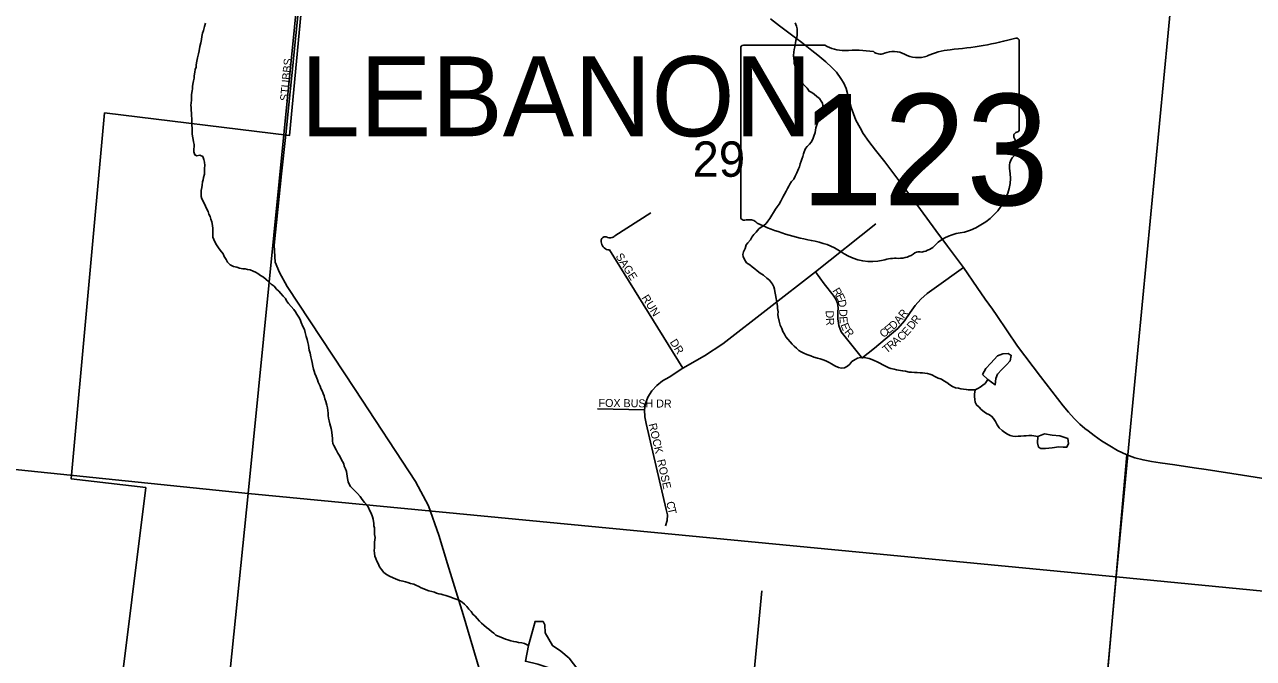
# Model space of a CAD drawing. Extents: x 1310247 to 1664935, y 284496 to 704931.
# Drawn here: x 1490025 to 1497704, y 520097 to 524060 of the extents above; entities that cross this region are included whole.
import ezdxf

# ---------------------------------------------------------------- set-up
doc = ezdxf.new("R2010")
doc.units = 0
for name, color, linetype in [('GM_P_State_Location', 7, 'Continuous'), ('GM_X_Airport_Class_2', 7, 'Continuous'), ('GM_X_Corporation_Text', 7, 'Continuous'), ('GM_X_County', 7, 'Continuous'), ('GM_X_County_Road_Text', 7, 'Continuous'), ('GM_X_County_Subdivision_Text', 7, 'Continuous'), ('GM_X_Interchange_Ramps', 7, 'Continuous'), ('GM_X_Interstate_Shield', 7, 'Continuous'), ('GM_X_Major_Lake_Text', 7, 'Continuous'), ('GM_X_Minor_River', 7, 'Continuous'), ('GM_X_Minor_River_Text', 7, 'Continuous'), ('GM_X_Rail_Line', 7, 'Continuous'), ('GM_X_State_Location', 7, 'Continuous'), ('GM_X_Unincorporated_Location', 7, 'Continuous'), ('GM_X_US_Location', 7, 'Continuous')]:
    doc.layers.add(name, color=color, linetype=linetype)

msp = doc.modelspace()

# ---------------------------------------------------------------- linework, layer by layer
at = {"layer": 'GM_X_Airport_Class_2'}
for p, q in [((1495027, 523930.7), (1494517.4, 523930.7)), ((1496240.5, 523404.2), (1496240.5, 523956.9)), ((1494500.3, 523912.5), (1494500.3, 522855.9)), ((1496240.3, 523404.3), (1496240.5, 523404.2))]:
    msp.add_line(p, q, dxfattribs=at)
for centre, major_axis, start_param, end_param in [((1494520.2, 523914.8), (20.2, 0), 1.712693, 3.28349), ((1495148.4, 524053.4), (195.5, 0), 4.042523, 4.731795), ((1495620.6, 525371.3), (1845.5, 0), 4.814394, 5.042369), ((1496221.2, 523959.2), (19.4, 0), 6.141152, 7.989035), ((1495213.2, 523337.5), (702, 0), 1.404758, 1.657858), ((1495372.6, 523920.3), (56.4, 0), 3.836095, 5.185415), ((1495455.4, 523798.1), (117.3, 0), 0.950623, 2.079405), ((1495606.8, 523965.6), (141.1, 0), 4.081561, 5.145723), ((1495856, 523608), (371.3, 0), 1.699011, 2.107814), ((1496236, 523363.6), (30, 0), 1.883978, 3.671073), ((1496219.8, 523402), (20.7, 0), 5.05454, 6.418171), ((1496045.2, 523293.7), (180, 0), 5.934695, 6.695948), ((1496309.9, 523172.9), (130.9, 0), 2.387724, 3.262537), ((1495724, 523102.5), (461.6, 0), 5.101752, 6.440018), ((1494520.4, 522853.6), (20.3, 0), 3.00124, 4.508301), ((1494523.5, 522961.7), (155.2, 0), 4.665946, 4.897461), ((1494555.2, 522794.9), (56, 0), 0.519207, 1.627899), ((1495261.8, 523744.3), (1332.7, 0), 4.195997, 4.488961), ((1494864.5, 522381.2), (417, 0), 0.823519, 1.323587), ((1495918.6, 522559.3), (252.8, 0), 1.647645, 2.488434), ((1495315.5, 522789.7), (264.6, 0), 4.026481, 4.996735), ((1495487.7, 522710.6), (141, 0), 4.691044, 5.507374), ((1495615.2, 522608.2), (39.7, 0), 1.147584, 2.315152), ((1495598.3, 522753.5), (149.1, 0), 4.937069, 5.64225), ((1495468.4, 522424.4), (217.4, 0), 1.495662, 1.94098)]:
    msp.add_ellipse(centre, major_axis=major_axis, ratio=0.8, start_param=start_param, end_param=end_param, dxfattribs=at)
at = {"layer": 'GM_X_Corporation_Text'}
for points in [[(1491706.3, 523847.1), (1491779.1, 524569.3), (1491780.9, 524586.9)], [(1491668.6, 523477.3), (1491703.9, 523823.1), (1491706.3, 523847.1)]]:
    msp.add_lwpolyline(points, dxfattribs=at)
at = {"layer": 'GM_X_County'}
for points in [[(1491905.7, 525995.7), (1491422.7, 521127.7), (1486183.9, 521667.6), (1486747.2, 526552.2)], [(1491905.7, 525995.7), (1497307.8, 525426.7), (1496845.7, 520606.4), (1491422.7, 521127.7)], [(1502528.3, 524873.1), (1502005.1, 520103.9), (1496845.7, 520606.4), (1497307.8, 525426.7)], [(1486183.9, 521667.6), (1491422.7, 521127.7), (1490846.7, 515461.6), (1485560.1, 516006.4)], [(1491422.7, 521127.7), (1496845.7, 520606.4), (1496329.6, 514931.2), (1490846.7, 515461.6)], [(1496845.7, 520606.4), (1502005.1, 520103.9), (1501457.6, 514459.3), (1496329.6, 514931.2)]]:
    msp.add_lwpolyline(points, close=True, dxfattribs=at)
at = {"layer": 'GM_X_County_Road_Text'}
for points in [[(1491657.6, 523371.7), (1491666.2, 523454), (1491668.6, 523477.3)], [(1492897.6, 519928.5), (1492765.2, 520370.4), (1492667.7, 520688.9), (1492614, 520867.8), (1492549.6, 521050.3), (1492469.1, 521202.4), (1492091.4, 521778.4), (1491665.5, 522422.1), (1491617.4, 522508.6), (1491591.8, 522574.2), (1491585.4, 522679.9), (1491631.8, 523127.4), (1491657.6, 523371.7)]]:
    msp.add_lwpolyline(points, dxfattribs=at)
at = {"layer": 'GM_X_County_Subdivision_Text'}
msp.add_lwpolyline([(1496579.5, 517943.7), (1496592.9, 517970.6), (1496773.6, 519789.2), (1496913.8, 521369.4)], dxfattribs=at)
at = {"layer": 'GM_X_Interstate_Shield'}
msp.add_lwpolyline([(1497886.8, 521203.6), (1497635.7, 521243.2), (1497408.9, 521277.9), (1497334.3, 521289.3), (1497212.4, 521306.8), (1497122.2, 521319.6), (1497067.6, 521327.7), (1497014.6, 521338.2), (1496962.2, 521351.5), (1496913.8, 521369.4), (1496855.9, 521397), (1496806.6, 521426.8), (1496755.6, 521457.5), (1496709, 521490.2), (1496671.9, 521518.7), (1496651.4, 521535.1), (1496619.8, 521562.1), (1496584, 521597.1), (1496548.8, 521635.9), (1496516.3, 521675.5), (1496374.6, 521858.5), (1496229.2, 522048.7), (1496100.1, 522240.5), (1496072.9, 522280.1), (1496028.5, 522342.5), (1495977.7, 522416.5), (1495892.8, 522540.1), (1495792.6, 522675.2), (1495719.8, 522772.7), (1495624.3, 522904.2), (1495520.4, 523043.1), (1495401.1, 523201.6), (1495343.1, 523274.4), (1495301.3, 523329.2), (1495266.5, 523379.6), (1495246.3, 523413.3), (1495220.8, 523462), (1495191.4, 523541.4), (1495158.8, 523659.3), (1495145.1, 523692.8), (1495127, 523722.4), (1495098.3, 523761.8), (1495070.1, 523791.1), (1495033, 523826.5), (1494982, 523868.7), (1494945.1, 523897.3), (1494881.6, 523947.1), (1494843.2, 523976), (1494801.1, 524008.6), (1494743.3, 524052.5), (1494687.4, 524096.1)], dxfattribs=at)
at = {"layer": 'GM_X_Major_Lake_Text'}
msp.add_lwpolyline([(1492739.1, 528236.4), (1492590.2, 527999.6), (1492590.3, 527654.3), (1492476.8, 526937.1), (1492510.1, 526911), (1492341.2, 526765.3), (1492143.3, 526534), (1492001.5, 526351.8), (1491952.5, 526265.9), (1491938.5, 526244.9), (1491908, 526192.6), (1491792.4, 526046.4), (1491737.7, 525997.1), (1492532.3, 525911.1), (1492426.8, 525068.9), (1492543.5, 525023), (1492464.3, 524267.8), (1491785.8, 524474.8), (1491679.9, 523365.5), (1490524.9, 523507.3), (1490317, 521219.5), (1490783, 521164.7), (1490518, 519041.9)], dxfattribs=at)
at = {"layer": 'GM_X_Minor_River'}
for points in [[(1496011.7, 521872.7), (1496045, 521839.8), (1496090.4, 521806.6), (1496095.4, 521846.6), (1496104.1, 521874.5), (1496133, 521903.9), (1496161.8, 521933.3), (1496184.5, 521956.9), (1496191.4, 521990.8), (1496171.6, 522003.3), (1496137.4, 522000.2), (1496104.9, 521988.9)], [(1496104.9, 521988.9), (1496063.6, 521943.7), (1496032.7, 521910.3), (1496011.7, 521872.7)], [(1496446.4, 521492.8), (1496398.4, 521500), (1496357.9, 521484.9), (1496354.9, 521444.9)], [(1496354.9, 521444.9), (1496360.2, 521418.6), (1496376.1, 521410.2), (1496404.2, 521409.5), (1496446.5, 521412.5), (1496488.9, 521419.5), (1496514.9, 521416.9), (1496539.1, 521418.3), (1496549.6, 521440.1), (1496544.4, 521472.4), (1496494.5, 521487.7), (1496446.4, 521492.8)], [(1493175.3, 520176.7), (1493154.8, 520078.8), (1493232.7, 520060.9), (1493300.5, 520037.2), (1493373.4, 519981.2), (1493430.6, 519933.7), (1493484.5, 519922.3), (1493493.9, 519976.3), (1493483.1, 520026.7), (1493428.6, 520098.3), (1493377.4, 520141.7), (1493324, 520177.1), (1493277.7, 520256.5), (1493276.9, 520306.7), (1493265.4, 520327.1)], [(1493265.4, 520327.1), (1493215.2, 520328.3), (1493175.3, 520176.7)]]:
    msp.add_lwpolyline(points, dxfattribs=at)
at = {"layer": 'GM_X_Minor_River_Text'}
for points in [[(1491156.2, 524069.1), (1491149.5, 524047.3), (1491142.7, 524023.4), (1491138.1, 524005.5), (1491133.4, 523985.7), (1491130.7, 523965.7), (1491126.1, 523945.8), (1491121.2, 523921.9), (1491116.4, 523896), (1491111.7, 523876.1), (1491106.9, 523852.2), (1491102.2, 523830.3), (1491097.4, 523808.4), (1491097, 523794.4), (1491092.4, 523778.5), (1491089.9, 523762.5), (1491085.1, 523738.6)], [(1494841.4, 524069.7), (1494848.8, 524049.4), (1494852.2, 524033.3), (1494853.7, 524017.2), (1494853, 523995.2), (1494850.4, 523977.2), (1494845.8, 523959.3), (1494843.3, 523945.4), (1494838.5, 523921.5), (1494833.9, 523903.6), (1494831.4, 523887.6), (1494830.7, 523865.6), (1494832.1, 523847.5), (1494833.5, 523831.4), (1494835.1, 523817.4), (1494840.5, 523799.2), (1494846, 523783), (1494851.4, 523762.8), (1494858.8, 523742.5), (1494866.3, 523728.2), (1494877.8, 523709.8), (1494885.3, 523695.6), (1494902.7, 523675), (1494916.4, 523662.6), (1494927.9, 523644.2), (1494945.7, 523635.6), (1494959.4, 523625.2), (1494977, 523610.6), (1494992.6, 523598.1), (1495004.2, 523581.7)], [(1491085.1, 523738.6), (1491084.6, 523724.6), (1491080.1, 523708.7), (1491077.3, 523686.8), (1491074.9, 523672.8), (1491074.4, 523658.8), (1491071.9, 523644.9), (1491069.2, 523622.9), (1491068.5, 523602.9), (1491068.1, 523588.9), (1491067.4, 523568.8), (1491065, 523554.9), (1491066.5, 523540.8), (1491065.9, 523522.8), (1491067.5, 523508.7), (1491068.9, 523490.6), (1491070.2, 523470.5), (1491071.6, 523452.5), (1491070.9, 523430.5), (1491072.3, 523412.4), (1491071.7, 523392.4), (1491073.1, 523376.3), (1491074.7, 523362.2), (1491078, 523340.1), (1491081.5, 523325.9), (1491085, 523309.8), (1491084.6, 523295.8), (1491082.1, 523281.8), (1491083.5, 523263.7), (1491088.9, 523245.5), (1491102.8, 523239.1), (1491121, 523242.5), (1491138.8, 523234), (1491146.2, 523215.7), (1491149.7, 523199.6), (1491151, 523179.5), (1491150.5, 523161.5), (1491149.9, 523145.4), (1491149.3, 523125.4), (1491144.5, 523103.5), (1491142.1, 523089.6), (1491137.6, 523075.7), (1491134.9, 523055.7), (1491132.5, 523041.8), (1491129.8, 523021.8), (1491129.1, 523001.8), (1491128.6, 522985.8), (1491134.1, 522969.6), (1491143.5, 522951.3), (1491156.7, 522924.8), (1491164.2, 522906.5), (1491171.7, 522890.3), (1491177.2, 522874.1), (1491184.7, 522859.8), (1491190.2, 522843.6), (1491195.7, 522827.4), (1491198.9, 522803.3), (1491202.4, 522785.1), (1491201.8, 522769.1), (1491201.2, 522751.1), (1491202.6, 522731), (1491208.2, 522716.8), (1491213.6, 522700.6), (1491225.1, 522682.2), (1491236.5, 522663.8), (1491248.1, 522649.5), (1491265.5, 522626.9), (1491273, 522610.6), (1491284.4, 522590.2), (1491293.9, 522573.9), (1491309.4, 522557.4), (1491331.1, 522546.7), (1491351.1, 522542.1), (1491369, 522537.5), (1491389, 522532.9), (1491403, 522532.5), (1491418.9, 522528), (1491434.9, 522525.5), (1491454.8, 522518.8), (1491468.7, 522512.4), (1491482.4, 522504), (1491500.1, 522491.4), (1491517.9, 522480.8), (1491535.5, 522466.3), (1491549.1, 522453.8), (1491566.6, 522437.2), (1491584.3, 522424.7), (1491599.8, 522406.2), (1491613.4, 522393.7), (1491627, 522379.3), (1491640.5, 522360.8), (1491656.1, 522346.3), (1491661.6, 522332.1), (1491675.2, 522315.7), (1491690.6, 522297.1), (1491708.1, 522278.6), (1491717.7, 522264.3), (1491727.2, 522249.9), (1491738.6, 522229.5), (1491748.2, 522215.2), (1491753.6, 522197)], [(1495004.2, 523581.7), (1495011.7, 523567.4), (1495013.3, 523553.4), (1495012.6, 523533.3), (1495007.9, 523513.4), (1494999.1, 523489.7), (1494988.3, 523466), (1494981.8, 523452.1), (1494977.3, 523438.2), (1494970.5, 523414.4), (1494968.1, 523400.4), (1494965.5, 523384.5), (1494956.8, 523362.7), (1494950.1, 523342.9), (1494941.5, 523325.1), (1494931, 523311.4), (1494916.5, 523297.8), (1494906, 523284.1), (1494897.3, 523264.3), (1494892.8, 523250.5), (1494888.2, 523234.6), (1494881.7, 523218.8), (1494877.2, 523204.9), (1494872.7, 523189), (1494868.1, 523171.1), (1494861.6, 523157.2), (1494850.8, 523133.5), (1494840, 523111.8), (1494831.4, 523094), (1494818.8, 523078.4), (1494808.2, 523062.7), (1494801.8, 523048.9), (1494793.3, 523035.1), (1494784.6, 523017.3), (1494774, 522999.6), (1494763.3, 522979.9), (1494750.5, 522956.3), (1494739.8, 522936.6), (1494729.2, 522920.9), (1494718.7, 522905.1), (1494706, 522885.5), (1494695.3, 522867.8), (1494682.6, 522848.1), (1494670, 522830.5), (1494659.5, 522816.8), (1494645, 522803.2), (1494628.6, 522793.7), (1494614.1, 522782.1), (1494597.4, 522762.6), (1494582.8, 522747), (1494570.3, 522731.4), (1494561.6, 522713.6), (1494545, 522696.1), (1494534.5, 522682.4), (1494527.8, 522660.5), (1494517, 522638.8), (1494514.5, 522622.9), (1494516, 522608.8), (1494523.4, 522590.5), (1494536.8, 522570.1), (1494556.5, 522557.5), (1494572.2, 522545), (1494587.8, 522532.5), (1494603.5, 522519.9), (1494621.1, 522505.4), (1494642.8, 522492.7), (1494664.3, 522474), (1494679.9, 522461.5), (1494699.2, 522436.8), (1494706.7, 522420.6), (1494712.3, 522406.4), (1494713.8, 522390.3), (1494717.1, 522370.1), (1494722.4, 522347.9), (1494723.9, 522333.9), (1494727.2, 522311.7), (1494730.8, 522297.6), (1494730.3, 522283.6), (1494733.7, 522263.4), (1494733.2, 522247.4), (1494734.7, 522233.3), (1494739.8, 522205.1), (1494747, 522180.9), (1494756.4, 522158.5), (1494763.8, 522140.3), (1494773.3, 522123.9), (1494782.8, 522107.6), (1494794.4, 522093.2), (1494809.9, 522076.7), (1494821.5, 522062.3), (1494835.2, 522049.9), (1494848.7, 522035.5), (1494864.4, 522022.9), (1494878.2, 522014.5), (1494894, 522006), (1494913.8, 521997.4), (1494937.6, 521988.6), (1494957.4, 521980), (1494979.3, 521973.3), (1494997.3, 521970.7), (1495015.2, 521964.2)], [(1491753.6, 522197), (1491764.9, 522172.6), (1491774.3, 522152.3), (1491779.7, 522134.1), (1491784.9, 522109.9), (1491790.4, 522091.7), (1491795.7, 522071.5), (1491799.2, 522055.3), (1491802.7, 522039.2), (1491804.2, 522023.1), (1491809.6, 522004.9), (1491814.9, 521982.7), (1491818.4, 521966.6), (1491821.7, 521946.4), (1491827, 521924.2), (1491830.5, 521906.1), (1491836, 521891.9), (1491839.6, 521877.8), (1491847, 521859.5), (1491856.4, 521839.2), (1491859.9, 521825), (1491873.1, 521798.6), (1491876.7, 521784.4), (1491884.2, 521770.2), (1491891.7, 521753.9), (1491897.2, 521737.7), (1491902.7, 521719.5), (1491908.2, 521703.3), (1491913.5, 521681.1), (1491918.9, 521662.9), (1491920.4, 521646.8), (1491921.8, 521630.8), (1491923.3, 521614.7), (1491924.8, 521598.6), (1491928.3, 521582.5), (1491933.7, 521564.2), (1491937.2, 521548.1), (1491940.8, 521534), (1491946.1, 521511.8), (1491947.3, 521487.7), (1491948.8, 521473.6), (1491950.3, 521457.5), (1491951.8, 521441.5), (1491957.3, 521427.3), (1491972.5, 521400.7), (1491983.9, 521380.3), (1491995.4, 521362), (1492004.7, 521341.6), (1492012.3, 521327.4), (1492019.9, 521313.1), (1492023.4, 521299), (1492030.9, 521282.7), (1492036.4, 521264.5), (1492041.5, 521236.3), (1492043, 521222.2), (1492048.3, 521200), (1492053.9, 521185.8), (1492061.4, 521171.6), (1492077, 521157.1), (1492090.6, 521142.6), (1492106.2, 521128.1), (1492121.7, 521109.6), (1492135.1, 521091.1), (1492150.6, 521072.6), (1492164.1, 521056.2), (1492173.6, 521039.9), (1492181.1, 521023.6), (1492190.6, 521005.3), (1492199.9, 520983), (1492203.4, 520966.8), (1492208.5, 520940.6), (1492208.1, 520926.6), (1492211.6, 520912.5), (1492211.2, 520898.4), (1492212.3, 520872.4), (1492215.7, 520852.2), (1492212.7, 520824.2), (1492212.1, 520804.2), (1492211.5, 520788.2), (1492211, 520772.2), (1492212.4, 520754.1), (1492213.8, 520736), (1492219.4, 520721.8), (1492226.9, 520705.6), (1492234.4, 520689.3), (1492243.8, 520669), (1492255.3, 520652.6), (1492270.8, 520634.1), (1492286.4, 520621.6), (1492306.2, 520611), (1492327.9, 520600.3), (1492343.8, 520593.8), (1492367.6, 520585), (1492389.6, 520580.3), (1492405.5, 520575.8), (1492419.4, 520571.4), (1492437.3, 520564.8), (1492457.2, 520560.2), (1492471.1, 520553.8), (1492488.9, 520547.2), (1492504.7, 520538.7)], [(1495015.2, 521964.2), (1495033.1, 521957.6), (1495052.8, 521947), (1495068.6, 521938.5), (1495088.3, 521925.8), (1495112, 521915.1), (1495130, 521912.5), (1495148.2, 521914), (1495168.6, 521923.4), (1495183.1, 521937), (1495195.6, 521952.6), (1495216.2, 521966), (1495230.5, 521973.6), (1495248.8, 521979), (1495262.8, 521978.6), (1495282.8, 521976), (1495302.8, 521971.3), (1495320.6, 521964.8), (1495334.5, 521960.3), (1495352.3, 521951.8), (1495370.2, 521943.2), (1495387.9, 521932.6), (1495409.6, 521921.9), (1495425.4, 521913.4), (1495439.4, 521909), (1495459.3, 521904.4), (1495473.3, 521901.9), (1495499.2, 521897.1), (1495513.2, 521894.7), (1495529.2, 521892.2), (1495553.2, 521887.5), (1495567.2, 521887), (1495587.2, 521884.4), (1495603.3, 521883.9), (1495621.4, 521883.3), (1495635.4, 521882.9), (1495651.4, 521880.4), (1495667.4, 521877.9), (1495681.3, 521873.5), (1495695.2, 521869), (1495717, 521858.3), (1495734.8, 521849.8), (1495754.7, 521843.2), (1495770.4, 521832.6), (1495788.1, 521822.1), (1495807.7, 521807.5), (1495823.5, 521797), (1495843.3, 521788.3), (1495861.3, 521785.8), (1495875.3, 521783.3), (1495893.3, 521780.8), (1495909.3, 521778.3), (1495923.2, 521775.8), (1495947.3, 521775.1), (1495965.5, 521776.5), (1495981.8, 521784), (1495996.2, 521793.6), (1496012.6, 521805.1), (1496027, 521814.7), (1496045, 521839.8)], [(1495965.5, 521776.5), (1495960.5, 521748.6), (1495962.1, 521734.6), (1495963.5, 521716.5), (1495964.9, 521698.4), (1495974.4, 521682.1), (1495990, 521667.6), (1496003.6, 521653.1), (1496021.2, 521638.5), (1496036.9, 521628), (1496050.8, 521621.6), (1496068.5, 521611), (1496080.1, 521596.6), (1496091.5, 521578.3), (1496102.9, 521557.9), (1496116.4, 521539.4), (1496133.9, 521520.9), (1496151.5, 521508.3), (1496167.3, 521499.8), (1496185.1, 521491.2), (1496201.1, 521486.7), (1496215, 521484.3), (1496233.2, 521485.7), (1496251.3, 521487.2), (1496269.4, 521488.6), (1496283.5, 521488.2), (1496301.6, 521489.6), (1496319.8, 521491.1), (1496357.9, 521484.9)], [(1492504.7, 520538.7), (1492520.6, 520532.2), (1492534.4, 520525.8), (1492552.3, 520519.2), (1492570.2, 520514.7), (1492586.2, 520510.2), (1492600.1, 520505.7), (1492614, 520501.3), (1492628, 520498.9), (1492641.9, 520494.4), (1492657.8, 520489.9), (1492675.7, 520483.4), (1492689.6, 520478.9), (1492703.5, 520474.5), (1492723.4, 520467.9), (1492741.3, 520461.3), (1492759, 520448.7), (1492774.6, 520436.2), (1492788.2, 520421.8), (1492801.7, 520405.3), (1492815.3, 520390.9), (1492826.8, 520372.5), (1492840.4, 520360.1), (1492854, 520345.6), (1492867.5, 520329.2), (1492881.2, 520316.7), (1492894.8, 520304.3), (1492912.5, 520289.7), (1492926.2, 520279.3), (1492943.8, 520264.7), (1492957.5, 520254.3), (1492971.2, 520241.8), (1492985, 520235.4), (1493000.9, 520228.9), (1493016.7, 520222.4), (1493030.6, 520217.9), (1493044.6, 520213.5), (1493064.4, 520206.9), (1493082.4, 520202.3), (1493096.4, 520199.9), (1493112.3, 520195.4), (1493132.4, 520194.8), (1493149.2, 520189.3), (1493175.3, 520176.7)]]:
    msp.add_lwpolyline(points, dxfattribs=at)
at = {"layer": 'GM_X_State_Location'}
for points in [[(1494139.5, 521910.5), (1493679.5, 522650.5), (1493670.8, 522651.7), (1493662.4, 522654.3), (1493654.5, 522658.2), (1493647.4, 522663.3), (1493641.1, 522669.6), (1493636, 522676.7), (1493632.1, 522684.6), (1493629.5, 522693), (1493628.3, 522701.8), (1493627.9, 522706.1), (1493628.2, 522710.5), (1493629.2, 522714.8), (1493630.9, 522718.8), (1493633.3, 522722.6), (1493636.2, 522725.8), (1493639.7, 522728.6), (1493643.5, 522730.7), (1493647.6, 522732.1), (1493652, 522732.9), (1493656.4, 522732.9), (1493660.7, 522732.2), (1493664.9, 522730.8), (1493668.8, 522728.7), (1493675.6, 522726.8), (1493682.7, 522726), (1493689.8, 522726.5), (1493696.7, 522728.1), (1493703.3, 522730.9), (1493709.3, 522734.7), (1493714.6, 522739.5), (1493938.3, 522882.3)], [(1494030.1, 520926.2), (1494041.7, 520959.3), (1494043.5, 520994.4), (1494035.4, 521028.6), (1493910.4, 521565.1), (1493900.6, 521607.1), (1493898.2, 521650.1), (1493904.7, 521691.4), (1493920.8, 521730), (1493945.8, 521768.8), (1493976.6, 521803.1), (1494012.6, 521832.1), (1494052.7, 521855), (1494139.5, 521910.5), (1494274.9, 521988.7), (1494389.5, 522063.3), (1494967.6, 522513), (1495344.3, 522813.4)], [(1495257.7, 521974.8), (1495336.3, 522037.2), (1495481.5, 522158.8), (1495523.3, 522207), (1495559.7, 522259.5), (1495590.2, 522303.1), (1495625.6, 522342.9), (1495665.3, 522378.3), (1495709, 522408.8), (1495892.8, 522540.1)], [(1495257.7, 521974.8), (1495252.4, 521981.7), (1495129.1, 522138), (1495113.7, 522177.3), (1495106.6, 522219), (1495108.3, 522261.2), (1495109.5, 522289.5), (1495104.8, 522317.3), (1495094.4, 522343.6), (1495078.8, 522367.1), (1495022.1, 522439.2), (1494967.6, 522513)], [(1493604.8, 521657.1), (1493898.2, 521650.1)], [(1494287.6, 518161), (1494331.3, 518599.5), (1494343.8, 518718.5), (1494357.2, 518793.6), (1494374.2, 518842.8), (1494401.9, 518915.3), (1494434.2, 518986), (1494455.6, 519027.1), (1494485.1, 519124.7), (1494500.4, 519196.2), (1494529.9, 519443.1), (1494631.9, 520518.5)]]:
    msp.add_lwpolyline(points, dxfattribs=at)

# ---------------------------------------------------------------- texts
at = {"layer": 'GM_P_State_Location'}
for s, rotation, p in [('SAGE', 302.34658, (1493716.6, 522611.2)), ('R', 301.79686, (1495071.1, 522395.4)), ('RUN', 302.47034, (1493879.3, 522351.6)), ('E', 297.11479, (1495091.5, 522362.7)), ('D', 282.26571, (1495106.4, 522334.5)), ('D', 270.59022, (1495032.1, 522271.6)), ('D', 270.67764, (1495116.2, 522281)), ('A', 51.10526, (1495491.4, 522184.1)), ('R', 51.02158, (1495519, 522218.3)), ('R', 53.01253, (1495600.5, 522183.7)), ('R', 274.07823, (1495032.7, 522224.3)), ('E', 274.00406, (1495116.9, 522233.9)), ('E', 292.18908, (1495123.2, 522182.3)), ('R', 309.45713, (1495144.8, 522135.8)), ('C', 38.47776, (1495392.4, 522098.7)), ('E', 38.45496, (1495423.4, 522123.4)), ('D', 43.53415, (1495454.6, 522148.4)), ('E', 48.07892, (1495538.9, 522108.7)), ('D', 52.37749, (1495573.3, 522148.3)), ('DR', 302.01276, (1494055.4, 522074.3)), ('R', 39.19565, (1495438.7, 522023.4)), ('A', 39.79044, (1495469.8, 522048.8)), ('C', 41.62491, (1495504.9, 522078.1)), ('T', 39.17601, (1495411.4, 522001.1)), ('FOX BUSH DR', 359.37074, (1493611.9, 521669.6)), ('ROCK', 283.32353, (1493924.5, 521561.1)), ('ROSE', 282.52727, (1493977.4, 521336.6)), ('C', 282.75799, (1494034.5, 521072.8)), ('T', 282.69772, (1494043.3, 521034.2))]:
    msp.add_text(s, height=50, rotation=rotation, dxfattribs=at).set_placement(p)
at = {"layer": 'GM_X_Airport_Class_2'}
msp.add_text('123', height=696.1, dxfattribs=at).set_placement((1494873.5, 522930.4))
at = {"layer": 'GM_X_Interchange_Ramps'}
msp.add_text('LEBANON', height=500, rotation=0.00001, dxfattribs=at).set_placement((1491749.9, 523361.4))
at = {"layer": 'GM_X_Rail_Line'}
msp.add_text('STUBBS', height=50, rotation=84.5063, dxfattribs=at).set_placement((1491670.8, 523579.4))
at = {"layer": 'GM_X_Unincorporated_Location'}
for s in ['s', 'r']:
    msp.add_text(s, height=1, dxfattribs=at).set_placement((1495350.8, 523314))
msp.add_text('123', height=1, rotation=0.00001, dxfattribs=at).set_placement((1494997.8, 523241.2))
at = {"layer": 'GM_X_US_Location'}
msp.add_text('29', height=221, rotation=0.00001, dxfattribs=at).set_placement((1494199.2, 523108.1))

doc.saveas('drawing.dxf')
